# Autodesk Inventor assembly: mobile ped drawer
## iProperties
Created: 2005-05
Part Number: mobile ped drawer
Document SubType Name: Assembly
Designer: a.campbell
Manufacturer: Standard
Standards Organization: Custom
B_Out_Length: 1.0 mm
B_Out_Width: 1.0 mm
B_Out_Thickness: 1.0 mm
LENGTH: 1.0 mm
WIDTH: 1.0 mm
THICKNESS: 1.0 mm
Author: a.campbell
